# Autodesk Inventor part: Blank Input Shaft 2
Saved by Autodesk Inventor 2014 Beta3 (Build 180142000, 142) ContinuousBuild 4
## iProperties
Created: 2011-01
Part Number: Blank Input Shaft 2
Material: Steel
Document SubType Name: Modeling
Designer: Beta-8540w
Density: 1 g/cm^3
Appearance: Steel
CustomPartVersion: 1
Author: Beta-8540w
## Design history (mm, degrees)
sketch "Main Sketch"
  geometry: L1 (0, 0)-(43, 0) reference; L2 (0, 0)-(0, 45); L3 (12, 45)-(12, 6); L4 (0, 45)-(12, 45); L5 (15, 6)-(15, 5); L6 (12, 6)-(15, 6); L7 (43, 5)-(43, 0); L8 (15, 5)-(43, 5)
  constraints: 16 end point, 5 horizontal, 4 vertical
  dimensions: "d3" = 90 diameter of L4 L1 (derived); "d4" = 12 diameter of L6 L1 (derived); "d5" = 10 diameter of L8 L1 (derived)
revolve "Revolution1" sketch "Main Sketch" stored, may be unused: angle "d6" = 0 deg
chamfer "Chamfer1" distance "d7" = 0.5; stored, may be unused: second distance "d8" = 0.125, angle "d9" = 45 deg
node "Retaining Ring Groove1"
body "Solid1"
feature "iFeature27:1"
other parameters: "d0" = 0, "d1" = 0, "d2" = 0
